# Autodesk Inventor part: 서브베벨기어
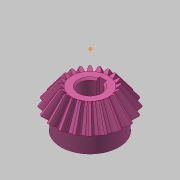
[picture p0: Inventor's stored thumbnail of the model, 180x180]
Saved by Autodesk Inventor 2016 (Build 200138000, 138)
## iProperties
Created: 2018-09
Part Number: 서브베벨기어
Material: 강철, 탄소
Document SubType Name: Modeling
Categories: <?xml version="1.0" encoding="UTF-16"?> <MemberInstance><Categories><FamilyTemplate><FamilyTemplateParameter ValueType="xs:double" Id="1" ObjectReferenceKey="da
Mass: 135.037 g
Surface Area: 63.6444 cm^2
Volume: 17.1585 cm^3
Density: 7.87 g/cm^3
Appearance: 분홍색
CustomPartVersion: 1
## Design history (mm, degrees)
node "맨 위 점"
node "메쉬 평면2"
sketch "톱니 본체 스케치"
  geometry: L1 (0, 0)-(18.003, -31.331); L2 (18.003, -31.331)-(21.664, -28.891); L3 (21.664, -28.891)-(0, 0); L4 (20, -30)-(0, 0); L5 (10.813, -18.818)-(13.012, -17.352); L6 (18.003, -31.331)-(10.813, -18.818); L7 (21.664, -28.891)-(13.012, -17.352); L8 (0, -39.387)-(0, 6.564) reference; L9 (0, -30)-(21.664, -30)
  constraints: 16 end point, 4 point on line, 3 perpendicular, 2 collinear, 1 horizontal alignment, 1 vertical alignment
  dimensions: "d0" = 40 diameter of L4.start L8 (= da_de); "d1" = 36.00616 diameter of L1.end L8 (= da_dfe); "d2" = 43.3282 diameter of L2.end L8 (= da_dae); "d3" = 14.4 distance between parallel lines of L2 L5 (= da_b); "d4" = 28.8906 vertical distance of L2.end L1.start (= da_ve)
revolve "톱니 본체" sketch "톱니 본체 스케치" stored, may be unused: angle "d5" = 90 deg
node "시작점"
node "톱니 평면"
sketch "시작 스케치"
  geometry: L1 (0, -23.505)-(0, 10.645) reference; L2 (-0.834, -2.928)-(0.834, -2.928); A1 r 8.898 centre (-9.698, -3.713) between (-0.834, -2.928) and (-3.903, 3.04); A2 r 8.898 centre (9.698, -3.713) between (3.903, 3.04) and (0.834, -2.928); A3 r 27.357 centre (0, -24.037) between (3.903, 3.04) and (-3.903, 3.04); 1 further point
  constraints: 6 point on circle, 3 centre point, 3 symmetric about line, 2 end point, 1 coincident, 1 perpendicular, 1 other
  dimensions: "d7" = 8.89846 radius of A1 (= fd_rr); "d8" = 9.69794 horizontal distance of point (0, -24.037) A1.centre (= fd_x); "d9" = 20.32439 vertical distance of point (0, -24.037) A1.centre (= fd_y); "d57" = 27.35701 radius of A3 (= 0.5 x fd_dva + 0.3 x da_he); "d58" = 21.10901 distance from line of A3.centre L2 (= 0.5 x fd_dva - 1.12 x da_he)
node "끝점"
  node "끝 평면"
sketch "3D 스케치 오른쪽"
  node "Helical Curve Right" dims "d65" = 229.90621 (computed from da_dm, da_delta, da_beta), "d66" = 31.5, "d67" = 40 (= da_de), "d68" = -5.88003 (= -da_delta), "d69" = 12.16458 (computed from fd_loft, da_delta)
node "끝 평면 오른쪽"
sketch "끝 스케치 오른쪽"
  geometry: L1 (0, -22.649)-(0, 12.15) reference; L2 (-0.497, -1.72)-(0.497, -1.72); A1 r 5.299 centre (-5.775, -2.187) between (-0.497, -1.72) and (-2.324, 1.834); A2 r 5.299 centre (5.775, -2.187) between (2.324, 1.834) and (0.497, -1.72); A3 r 16.291 centre (0, -14.29) between (2.324, 1.834) and (-2.324, 1.834); 1 further point
  constraints: 6 point on circle, 3 centre point, 3 symmetric about line, 2 end point, 1 coincident, 1 perpendicular, 1 other
  dimensions: "d70" = 5.77526 horizontal distance of A3.centre A1.centre (computed from fd_x, fd_ratio); "d71" = 12.10346 vertical distance of point (0, -14.29) A1.centre (computed from fd_y, fd_ratio); "d72" = 5.29916 radius of A1 (computed from fd_rr, fd_ratio); "d73" = 12.57071 distance from line of point (0, -14.29) L2 (computed from d58, fd_ratio); "d74" = 16.29149 radius of A3 (computed from d57, fd_ratio)
feature "로프트 오른쪽" sketch "끝 스케치 오른쪽" dims "d75" = 0, "d77" = 0, "d79" = 0, "d80" = 90 deg, "d85" = 20, "d92" = 90 deg, "d93" = 90 deg, "da_teethtype" = 0 [user parameter]
sketch "3D 스케치 왼쪽"
  node "Helical Curve Left" dims "d26" = 229.90621 (computed from da_dm, da_delta, da_beta), "d27" = 12.16458 (computed from fd_loft, da_delta), "d28" = 40 (= da_de), "d29" = -5.88003 (= -da_delta)
node "끝 평면 왼쪽"
sketch "끝 스케치 왼쪽" dims "d56" = 10.82768 (derived)
  geometry: L1 (0, -35.087)-(0, 18.089) reference; L2 (-0.497, -1.716)-(0.497, -1.716); A1 r 5.299 centre (-5.775, -2.183) between (-0.497, -1.716) and (-2.324, 1.838); A2 r 5.299 centre (5.775, -2.183) between (2.324, 1.838) and (0.497, -1.716); A3 r 16.291 centre (0, -14.287) between (2.324, 1.838) and (-2.324, 1.838); 2 further points; 1 other entity
  constraints: 6 point on circle, 3 centre point, 3 symmetric about line, 2 end point, 1 coincident, 2 other
  dimensions: "d30" = 5.29916 radius of A1 (computed from fd_rr, fd_ratio); "d31" = 5.77526 horizontal distance of point (0, -14.287) A1.centre (computed from fd_x, fd_ratio); "d32" = 12.10346 vertical distance of A1.centre point (0, -14.287) (computed from fd_y, fd_ratio); "d61" = 16.29149 radius of A3 (computed from d57, fd_ratio); "d62" = 12.57071 distance from line of point (0, -14.287) L2 (computed from d58, fd_ratio)
feature "로프트 왼쪽" sketch "끝 스케치 왼쪽" dims "d35" = 0, "d37" = 0, "d39" = 0, "d40" = 90 deg, "d84" = 10, "d90" = 90 deg, "d91" = 90 deg, "da_teethtype" = 0 [user parameter]
sketch "본체 스케치"
  geometry: L1 (0, -35.038)-(0, -19.531) reference; L2 (18.003, -31.331)-(10.813, -18.818) reference; L3 (10.813, -18.818)-(0, -18.818); L4 (18.003, -31.331)-(0, -31.331)
  constraints: 4 end point, 2 perpendicular, 2 point on line
revolve "본체 고정" sketch "본체 스케치" stored, may be unused: angle "d46" = 90 deg
feature "피치 지름" dims angle "d47" = 90 deg
sketch "스케치8"
  geometry: C1 r 17 at (0, 0); 1 further point
  constraints: 1 centre point, 1 coincident
  dimensions: "d94" = 34 diameter of C1
extrude "돌출1" join sketch "스케치8" distance "d95" = 10; taper "d96" = 0 deg
sketch "스케치9"
  geometry: 1 further point
hole "구멍1" sketch "스케치9" at (0, 0) diameter "d97" = 12; stored, may be unused: countersink angle "d101" = 90 deg, drill point angle "d103" = 118 deg; dims "d98" = 6, "d99" = 4, "d100" = 2, "d102" = 8
sketch "스케치10"
  geometry: 1 further point
sketch "스케치11"
  geometry: 1 further point
sketch "스케치12"
  geometry: L1 (-2, 5.657)-(-2, 7.8); L2 (-2, 7.8)-(2, 7.8); L3 (2, 7.8)-(2, 5.657); A1 r 6 centre (0, 0) between (-2, 5.657) and (2, 5.657) reference; 1 further point
  constraints: 6 end point, 2 parallel, 2 point on circle, 1 perpendicular, 1 vertical
  dimensions: "d104" = 4 distance of L1.end L2.end; "d105" = 13.8 dimension on A1 L2
extrude "돌출2" cut sketch "스케치12" stored distance "d106" = 7; taper "d107" = 0 deg
chamfer "모따기1" distance "d108" = 1; stored, may be unused: second distance "d109" = 2, angle "d110" = 45 deg
body "Solid1"
feature "로프트" dims "d17" = 0, "d18" = 90 deg, "d19" = 0, "d20" = 90 deg, "d89" = 0, "da_teethtype" = 0 [user parameter]
pattern_circular "원형 패턴" dims angle "d22" = 360 deg, "d88" = 0, "da_teethtype" = 0 [user parameter]
pattern_circular "원형 패턴 오른쪽" dims angle "d82" = 360 deg, "da_teethtype" = 0 [user parameter]
pattern_circular "원형 패턴 왼쪽" dims angle "d42" = 360 deg, "da_teethtype" = 0 [user parameter]
sketch "끝 스케치"
  geometry: L1 (0, -15.359)-(0, 6.983) reference; L2 (-0.497, -1.72)-(0.497, -1.72); A1 r 5.299 centre (-5.775, -2.187) between (-0.497, -1.72) and (-2.324, 1.834); A2 r 5.299 centre (5.775, -2.187) between (2.324, 1.834) and (0.497, -1.72); A3 r 16.291 centre (0, -14.29) between (2.324, 1.834) and (-2.324, 1.834); 1 further point
  constraints: 6 point on circle, 3 centre point, 3 symmetric about line, 2 end point, 1 coincident, 1 other
  dimensions: "d12" = 5.29916 radius of A1 (computed from fd_rr, fd_ratio); "d15" = 5.77526 horizontal distance of A1.centre point (0, -14.29) (computed from fd_x, fd_ratio); "d16" = 12.10346 vertical distance of A1.centre point (0, -14.29) (computed from fd_y, fd_ratio); "d59" = 16.29149 radius of A3 (computed from d57, fd_ratio); "d60" = 12.57071 distance from line of A3.centre L2 (computed from d58, fd_ratio)
sketch "Sketch6"
  geometry: L1 (20, -30)-(0, 0) reference; L2 (0, -37.8)-(0, 6.3) reference
body "Srf1"
other parameters: "da_b" = 14.4 [user parameter; used in 2 equation terms], "da_de" = 40 [user parameter; used in 4 equation terms], "da_dae" = 43.3282 [user parameter; used in 2 equation terms], "da_dfe" = 36.00616 [user parameter; used in 1 equation term], "da_le" = 36.05551 [user parameter; used in 1 equation term], "da_omega" = 90 deg [user parameter; used in 1 equation term], "da_beta" = 0 [user parameter; used in 2 equation terms], "da_delta" = 5.88003 [user parameter; used in 8 equation terms], "da_alpha" = 20 deg [user parameter; used in 2 equation terms], "da_he" = 4.4 [user parameter; used in 4 equation terms], "da_ve" = 28.8906 [user parameter; used in 1 equation term], "fd_dv" = 48.07402 (computed from da_de, da_delta) [user parameter; used in 1 equation term], "fd_dva" = 52.07402 (computed from da_dae, da_delta) [user parameter; used in 3 equation terms], "fd_dvb" = 45.1748 (computed from fd_dv, da_alpha) [user parameter; used in 2 equation terms], "da_zv" = 240.37008 [user parameter; used in 1 equation term], "fd_loft" = 14.62 (= da_b + 0.05 x da_he) [user parameter; used in 4 equation terms], "fd_ratio" = 5.95514 (computed from da_le, fd_loft) [user parameter; used in 15 equation terms], "fd_rr" = 8.89846 (computed from fd_dd, fd_dvb) [user parameter; used in 6 equation terms], "fd_angle" = 0.66075 (computed from da_zv) [user parameter; used in 4 equation terms], "fd_x1" = 1.58709 (computed from da_dvw, fd_angle) [user parameter; used in 1 equation term], "fd_y1" = 23.98456 (computed from da_dvw, fd_angle) [user parameter; used in 1 equation term], "fd_x2" = 8.11084 (computed from fd_rr, fd_angle2, fd_angle) [user parameter; used in 1 equation term], "fd_y2" = 3.66016 (computed from fd_rr, fd_angle2, fd_angle) [user parameter; used in 1 equation term], "fd_x" = 9.69794 (= fd_x1 + fd_x2) [user parameter; used in 4 equation terms], "fd_y" = 20.32439 (= fd_y1 - fd_y2) [user parameter; used in 4 equation terms], "fd_angle2" = 3.57832 (computed from fd_dvb, fd_dd, da_alpha) [user parameter; used in 2 equation terms], "fd_dd" = 48.55402 (= fd_dva - 0.8 x da_he) [user parameter; used in 2 equation terms], "da_dvw" = 48.07402 [user parameter; used in 2 equation terms], "d11" = 14.62 (= fd_loft), "da_dm" = 32.01232 [user parameter; used in 2 equation terms], "da_x" = 0 [user parameter], "da_m" = 2 [user parameter], "d48" = 0, "d49" = 0, "d50" = 90 deg (= da_omega), "d51" = 9 deg (computed from da_z), "d52" = 0, "d53" = 0, "d54" = 0
